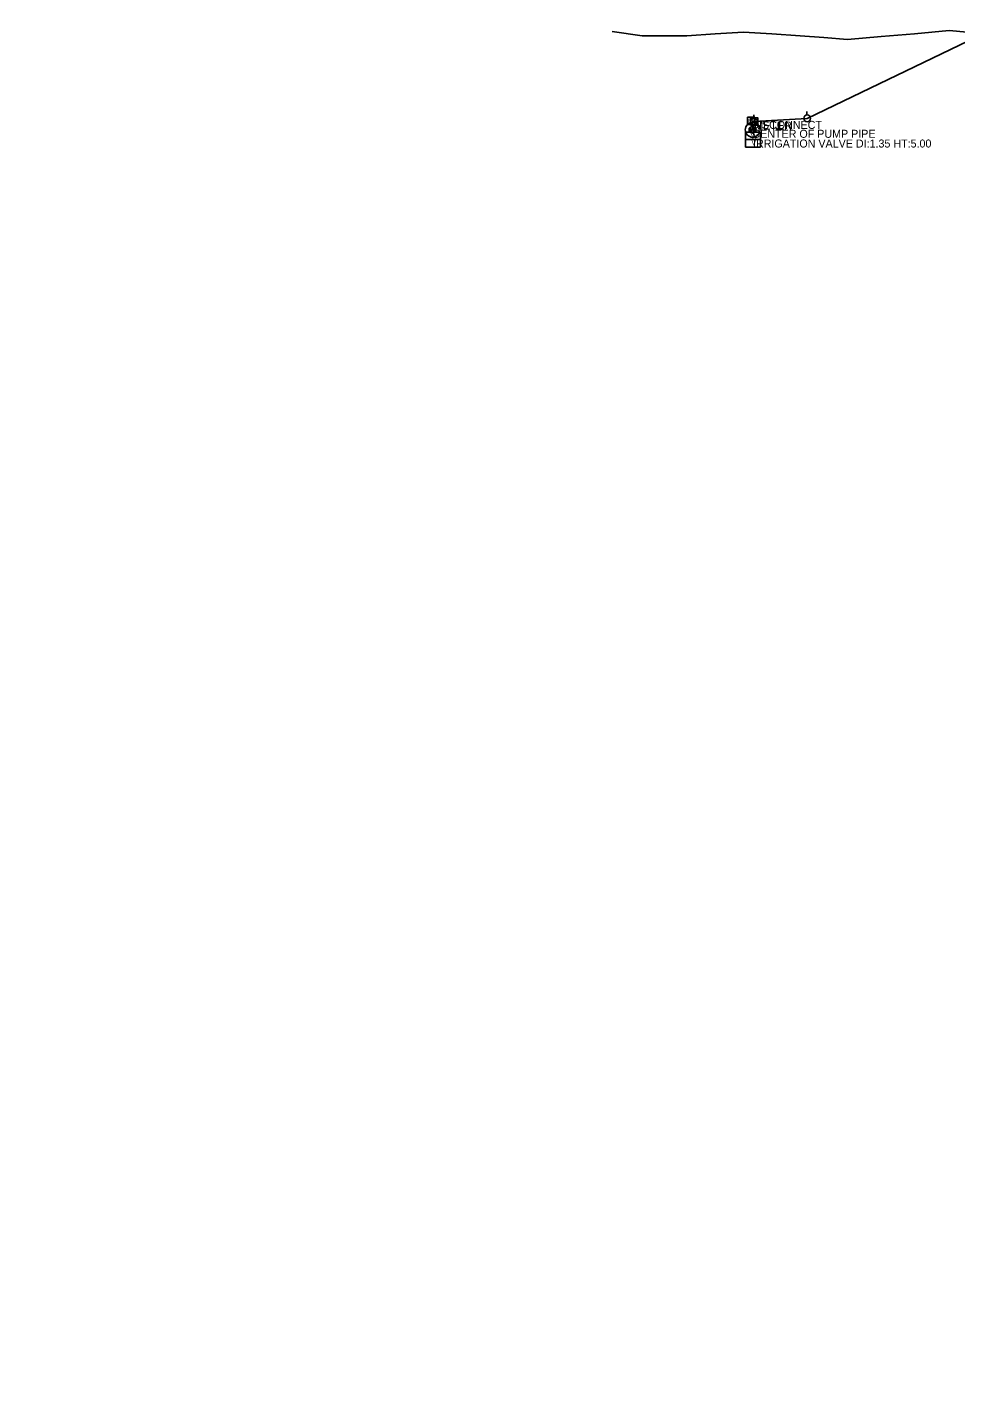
# Model space of a CAD drawing. Extents: x 1674300 to 1677920, y 225056 to 231852.
# Drawn here: x 1676544 to 1677124, y 228301 to 229147 of the extents above; entities that cross this region are included whole.
import ezdxf

# ---------------------------------------------------------------- set-up
doc = ezdxf.new("R2010")
doc.units = 0
for name, color, linetype in [('R_Horz Alg', 7, 'Continuous'), ('S_EDGE_CONCRETE', 7, 'Continuous'), ('S_ELECTRIC_UTILITIES', 7, 'Continuous'), ('S_ELECTRIC_UTILITIES_ANNOT', 7, 'Continuous'), ('S_EXIST_ROW', 7, 'Continuous'), ('S_EXISTING_ALIGNMENT', 7, 'Continuous'), ('S_STREAM', 7, 'Continuous'), ('S_UTILITY_POLE', 7, 'Continuous'), ('S_UTL_PT_SYM', 7, 'Continuous'), ('S_WATER_UTILITIES', 7, 'Continuous'), ('S_WATER_UTILITIES_ANNOT', 7, 'Continuous'), ('S_WATER_WELL_ANNOT', 7, 'Continuous')]:
    doc.layers.add(name, color=color, linetype=linetype)

msp = doc.modelspace()

# ---------------------------------------------------------------- linework, layer by layer
at = {"layer": 'R_Horz Alg'}
msp.add_arc((1675928.16, 228988.54), 1449, 296.0624, 0.80558, dxfattribs=at)
at = {"layer": 'S_EDGE_CONCRETE'}
msp.add_lwpolyline([(1676995.02, 229083.8), (1676994.98, 229082.04), (1676996.14, 229081.03), (1676997.58, 229080.98), (1676998.8, 229082.15), (1676998.7, 229083.76), (1676997.57, 229084.6), (1676996.22, 229084.77)], close=True, dxfattribs=at)
at = {"layer": 'S_ELECTRIC_UTILITIES'}
for p, q in [((1677278.13, 229208.63), (1677031.23, 229090)), ((1677031.23, 229090), (1676997.94, 229088.05))]:
    msp.add_line(p, q, dxfattribs=at)
for points in [[(1676994, 229086.15), (1676994, 229090.65), (1676998.5, 229090.65), (1676998.5, 229086.15)], [(1676995.91, 229085.75), (1676995.91, 229090.25), (1677000.41, 229090.25), (1677000.41, 229085.75)]]:
    msp.add_lwpolyline(points, close=True, dxfattribs=at)
at = {"layer": 'S_EXIST_ROW'}
msp.add_arc((1675926.71, 228989.39), 1410.53, 295.94359, 0.85682, dxfattribs=at)
at = {"layer": 'S_EXISTING_ALIGNMENT'}
msp.add_arc((1675926.71, 228989.39), 1450.53, 315.98862, 345.81316, dxfattribs=at)
at = {"layer": 'S_STREAM'}
msp.add_lwpolyline([(1677183.04, 229148.43), (1677170.36, 229146.92), (1677156.37, 229144.85), (1677142.38, 229142.77), (1677119.88, 229144.84), (1677098.3, 229142.91), (1677077.37, 229141.12), (1677056.44, 229139.33), (1677041.62, 229140.43), (1677026.8, 229141.54), (1677009.09, 229142.72), (1676991.39, 229143.9), (1676973.72, 229142.72), (1676956.05, 229141.55), (1676942.08, 229141.57), (1676928.12, 229141.58), (1676909.38, 229144.28)], dxfattribs=at)
at = {"layer": 'S_UTILITY_POLE'}
for p, q in [((1677031.11, 229092.14), (1677031.11, 229094.25)), ((1676997.81, 229090.19), (1676997.81, 229092.3)), ((1677013.87, 229087.68), (1677013.87, 229082.95))]:
    msp.add_line(p, q, dxfattribs=at)
for centre in [(1676997.94, 229088.05), (1677031.23, 229090)]:
    msp.add_circle(centre, 2.13, dxfattribs=at)
msp.add_arc((1677013.93, 229086.37), 3.41, 226.39718, 313.60282, dxfattribs=at)
at = {"layer": 'S_UTL_PT_SYM'}
for points in [[(1676997.94, 229088.05), (1676997.94, 229088.1), (1676997.94, 229088.05), (1676997.89, 229088.05), (1676997.94, 229088.05), (1676997.94, 229088), (1676997.94, 229088.05), (1676997.99, 229088.05)], [(1677031.23, 229090), (1677031.23, 229090.05), (1677031.23, 229090), (1677031.18, 229090), (1677031.23, 229090), (1677031.23, 229089.95), (1677031.23, 229090), (1677031.28, 229090)]]:
    msp.add_lwpolyline(points, dxfattribs=at)
at = {"layer": 'S_WATER_UTILITIES'}
for p, q in [((1676992.68, 229081.46), (1677002.1, 229081.46)), ((1676992.68, 229072.04), (1676992.68, 229081.46)), ((1676992.68, 229076.77), (1677002.1, 229076.77)), ((1676995.63, 229084.08), (1676996.29, 229081.6)), ((1676996.29, 229081.6), (1676997.1, 229084.08)), ((1676997.1, 229084.08), (1676998.15, 229081.6)), ((1676998.15, 229081.6), (1676998.73, 229084.12)), ((1677002.1, 229081.46), (1677002.1, 229072.04)), ((1677002.1, 229072.04), (1676992.68, 229072.04))]:
    msp.add_line(p, q, dxfattribs=at)
for centre, radius in [((1676997.19, 229082.82), 4.63), ((1676997.16, 229082.82), 2.13)]:
    msp.add_circle(centre, radius, dxfattribs=at)

# ---------------------------------------------------------------- texts
at = {"layer": 'S_ELECTRIC_UTILITIES'}
for p in [(1676994.31, 229087.2), (1676996.22, 229086.8)]:
    msp.add_text('BE', height=2.4, rotation=360, dxfattribs=at).set_placement(p)
at = {"layer": 'S_ELECTRIC_UTILITIES_ANNOT'}
for s, p in [('DISCONNECT', (1676996.27, 229083.4)), ('METER', (1676998.18, 229083))]:
    msp.add_text(s, height=5, rotation=360, dxfattribs=at).set_placement(p)
at = {"layer": 'S_WATER_UTILITIES'}
for s, p in [('W', (1676996.24, 229077.3)), ('V', (1676996.47, 229073.24))]:
    msp.add_text(s, height=3, rotation=360, dxfattribs=at).set_placement(p)
at = {"layer": 'S_WATER_UTILITIES_ANNOT'}
msp.add_text('IRRIGATION VALVE DI:1.35 HT:5.00', height=5, rotation=360, dxfattribs=at).set_placement((1676997.39, 229071.77))
at = {"layer": 'S_WATER_WELL_ANNOT'}
msp.add_text('CENTER OF PUMP PIPE', height=5, rotation=360, dxfattribs=at).set_placement((1676997.04, 229077.85))

doc.saveas('drawing.dxf')
